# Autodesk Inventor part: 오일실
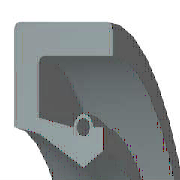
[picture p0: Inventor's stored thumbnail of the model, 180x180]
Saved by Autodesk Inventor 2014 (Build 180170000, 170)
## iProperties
IsCustomPart: 0
Created: 2016-05
Part Number: 오일실
Material: 고무
Description: 오일-실
Document SubType Name: Modeling
Standard: KS B 2804
Designer: mduedu
Standards Organization: KS
Language: ko-KR
Size Designation: S - 17 30 8
Categories: <MemberInstance><Categories><Category DisplayName="샤프트 부품" InternalName="7f7aeb1f-a693-4053-b835-cee3144e0d98" Mnemonic="SHFT"><Category DisplayName="실링" Intern
Density: 0.93 g/cm^3
Appearance: Rubber - Black - Version 1.1
Author: mduedu
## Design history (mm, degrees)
revolve "본체" stored, may be unused: angle "d17" = 90 deg
revolve "스프링1" stored, may be unused: angle "d18" = 90 deg
body "Solid1"
sketch "스케치1"
  geometry: L1 (0, 15)-(8, 15); L2 (8, 15)-(8, 13.75); L3 (8, 13.75)-(1.75, 13.75); L4 (0, 15)-(0, 10.6); L5 (0, 10.6)-(1.75, 10.25); L6 (1.75, 10.25)-(4.9, 8.5); L7 (4.9, 8.5)-(0, 8.5); L8 (6.3, 9.375)-(6.3, 10.6); L9 (0, 0)-(9.586, 0) reference; L10 (4.9, 8.5)-(6.3, 9.375); L11 (0, 18)-(0, -3) reference; L12 (-1.917, 0)-(11.503, 0) reference; L13 (4.2, 10.6)-(1.75, 11.09); L14 (1.75, 11.09)-(1.75, 13.75); L15 (6.3, 10.6)-(5.6, 10.6); C1 r 0.455 at (4.9, 10.6); A1 r 0.7 centre (4.9, 10.6) between (5.6, 10.6) and (4.2, 10.6)
  constraints: 26 end point, 5 horizontal alignment, 4 perpendicular, 2 centre point, 2 collinear, 2 horizontal, 2 parallel, 2 point on circle, 2 point on line, 2 vertical alignment, 1 coincident
  dimensions: "d0" = 30 diameter of L1 L9 (= SD2); "d1" = 18.75 diameter of L8.start L9 (= ABDM); "d2" = 1.25 distance of L1.end L2.end (computed from SD); "d3" = 0.91 diameter of C1 (= SPDI); "d4" = 1.4 diameter of A1 (= SPDA); "d5" = 17 diameter of L6.end L9 (= NND); "d6" = 20.5 diameter of L5.end L9 (= TKDM); "d7" = 21.2 diameter of L4.end L9 (= HLDM); "d8" = 4.9 distance from line of C1.centre L4 (= SPDST); "d9" = 6.3 distance between parallel lines of L8 L4 (= SDI); "d10" = 8 distance between parallel lines of L2 L4 (= SWDT); "d12" = 1.75 distance between parallel lines of L14 L4 (= SD)
fillet "모깎기1" dims "d11" = 0.3 (= RR)
other parameters: "SD2" = 30 [user parameter; used in 1 equation term], "SWDT" = 8 [user parameter; used in 1 equation term], "RR" = 0.3 [user parameter; used in 1 equation term], "SD" = 1.75 [user parameter; used in 2 equation terms], "NND" = 17 [user parameter; used in 1 equation term], "SPDA" = 1.4 [user parameter; used in 1 equation term], "SPDI" = 0.91 [user parameter; used in 1 equation term], "TKDM" = 20.5 [user parameter; used in 1 equation term], "HLDM" = 21.2 [user parameter; used in 1 equation term], "ABDM" = 18.75 [user parameter; used in 1 equation term], "SDI" = 6.3 [user parameter; used in 1 equation term], "SPDST" = 4.9 [user parameter; used in 1 equation term], "d13" = 0, "d14" = 0, "d15" = 0, "LAB" = 0.35 [user parameter]
